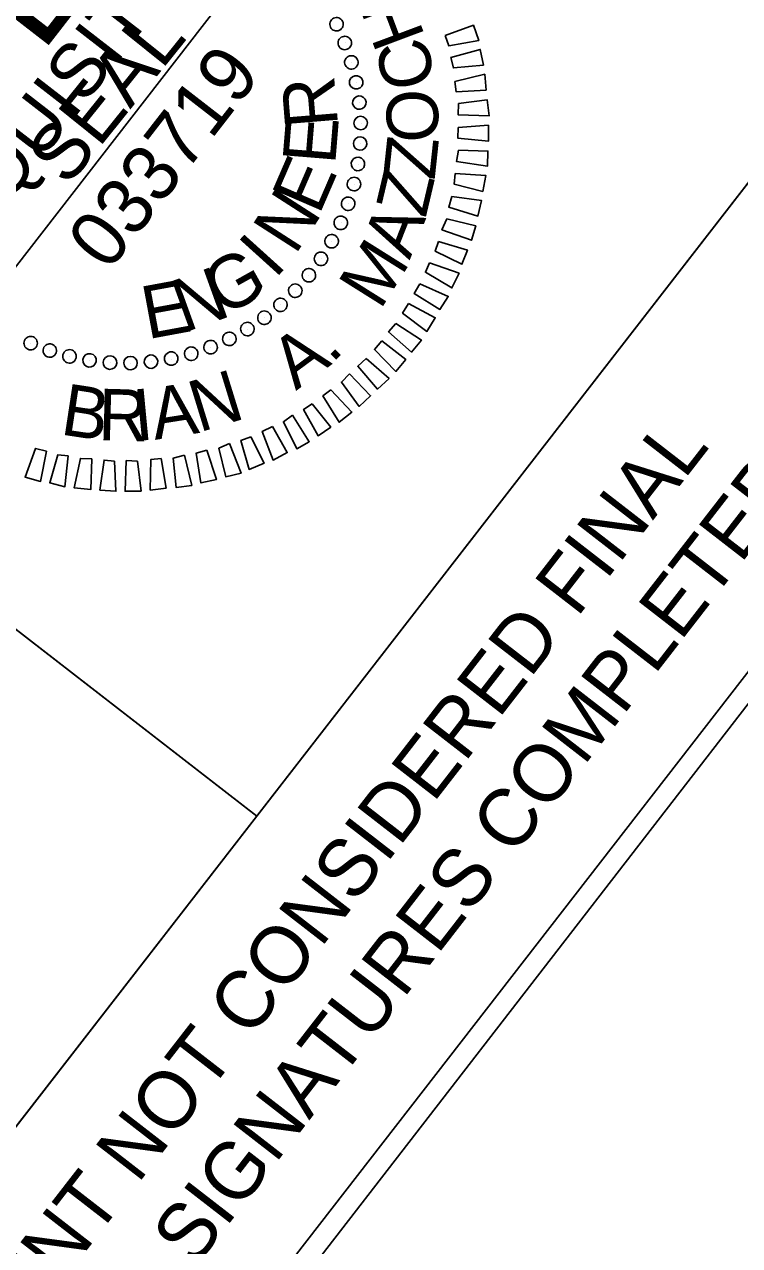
# Model space of a CAD drawing. Extents: x 2013373 to 2015284, y 444618 to 446636.
# Drawn here: x 2014451.4 to 2014527.7, y 446383.7 to 446513.9 of the extents above; entities that cross this region are included whole.
import ezdxf

# ---------------------------------------------------------------- set-up
doc = ezdxf.new("R2010")
doc.units = 0
for name, color, linetype in [('Old_Level_15', 7, 'Continuous'), ('Prop Conc 2ft 9in Curb and Gutter', 7, 'Continuous'), ('Prop Horizontal Alignment', 7, 'Continuous'), ('Prop Horizontal Alignment Tick Large', 7, 'Continuous'), ('Prop Noise Wall', 7, 'Continuous'), ('Scratch_Level_3', 7, 'Continuous')]:
    doc.layers.add(name, color=color, linetype=linetype)

msp = doc.modelspace()

# ---------------------------------------------------------------- linework, layer by layer
at = {"layer": 'Old_Level_15'}
for p, q in [((2014485.67, 446511.97), (2014485.67, 446511.97)), ((2014486.33, 446509.88), (2014486.33, 446509.88)), ((2014486.88, 446507.74), (2014486.88, 446507.74)), ((2014487.19, 446505.61), (2014487.19, 446505.61)), ((2014462.23, 446502.88), (2014462.23, 446502.88)), ((2014487.36, 446503.38), (2014487.36, 446503.38)), ((2014487.28, 446501.23), (2014487.28, 446501.23)), ((2014487.02, 446499.03), (2014487.02, 446499.03)), ((2014486.62, 446496.87), (2014486.62, 446496.87)), ((2014486.02, 446494.8), (2014486.02, 446494.8)), ((2014485.21, 446492.78), (2014485.21, 446492.78)), ((2014484.18, 446490.79), (2014484.18, 446490.79)), ((2014483.1, 446488.91), (2014483.1, 446488.91)), ((2014481.79, 446487.14), (2014481.79, 446487.14)), ((2014480.32, 446485.49), (2014480.32, 446485.49)), ((2014478.73, 446484.01), (2014478.73, 446484.01)), ((2014477.08, 446482.63), (2014477.08, 446482.63)), ((2014473.31, 446480.37), (2014473.31, 446480.37)), ((2014475.24, 446481.4), (2014475.24, 446481.4)), ((2014452.13, 446479.9), (2014452.13, 446479.9)), ((2014454.15, 446479.09), (2014454.15, 446479.09)), ((2014471.32, 446479.44), (2014471.32, 446479.44)), ((2014456.22, 446478.49), (2014456.22, 446478.49)), ((2014458.38, 446478.09), (2014458.38, 446478.09)), ((2014460.58, 446477.83), (2014460.58, 446477.83)), ((2014462.73, 446477.75), (2014462.73, 446477.75)), ((2014464.96, 446477.92), (2014464.96, 446477.92)), ((2014467.09, 446478.23), (2014467.09, 446478.23)), ((2014469.23, 446478.78), (2014469.23, 446478.78))]:
    msp.add_line(p, q, dxfattribs=at)
for points in [[(2014496.33, 446512.75), (2014499.33, 446513.84), (2014499.89, 446512.2), (2014496.69, 446511.65)], [(2014496.91, 446510.4), (2014500.05, 446511.26), (2014500.4, 446509.59), (2014497.2, 446509.29)], [(2014497.34, 446507.85), (2014500.53, 446508.61), (2014500.67, 446506.92), (2014497.49, 446506.73)], [(2014497.72, 446505.48), (2014500.8, 446505.87), (2014501.02, 446504.18), (2014497.69, 446504.3)], [(2014497.71, 446502.95), (2014500.93, 446503.17), (2014500.93, 446501.46), (2014497.65, 446501.8)], [(2014497.74, 446500.53), (2014500.88, 446500.42), (2014500.84, 446498.81), (2014497.54, 446499.29)], [(2014497.38, 446498.02), (2014500.64, 446497.83), (2014500.32, 446496.11), (2014497.27, 446496.9)], [(2014497.01, 446495.59), (2014500.2, 446495.13), (2014499.8, 446493.48), (2014496.69, 446494.44)], [(2014496.49, 446493.2), (2014499.58, 446492.45), (2014499.13, 446490.9), (2014495.96, 446492.03)], [(2014495.62, 446490.78), (2014498.69, 446489.85), (2014498.1, 446488.35), (2014495.25, 446489.73)], [(2014494.66, 446488.48), (2014497.79, 446487.38), (2014497.03, 446485.82), (2014494.21, 446487.5)], [(2014493.62, 446486.25), (2014496.64, 446484.92), (2014495.75, 446483.52), (2014493.01, 446485.21)], [(2014492.39, 446484.17), (2014495.26, 446482.64), (2014494.37, 446481.18), (2014491.77, 446483.13)], [(2014491.06, 446482.04), (2014493.78, 446480.25), (2014492.73, 446478.97), (2014490.28, 446481.12)], [(2014489.55, 446480.17), (2014492.11, 446478.18), (2014491.06, 446476.91), (2014488.77, 446479.26)], [(2014487.9, 446478.29), (2014490.34, 446476.14), (2014489.09, 446475.02), (2014487, 446477.47)], [(2014486.11, 446476.64), (2014488.36, 446474.32), (2014487.15, 446473.17), (2014485.25, 446475.78)], [(2014484.11, 446474.96), (2014486.37, 446472.57), (2014485.02, 446471.48), (2014483.27, 446474.29)], [(2014482.13, 446473.46), (2014484.12, 446470.97), (2014482.77, 446470.05), (2014481.21, 446472.85)], [(2014480.04, 446472.24), (2014481.82, 446469.4), (2014480.49, 446468.66), (2014479.06, 446471.54)], [(2014475.59, 446469.93), (2014477.01, 446467.12), (2014475.42, 446466.45), (2014474.53, 446469.55)], [(2014477.91, 446471.04), (2014479.47, 446468.25), (2014477.97, 446467.45), (2014476.8, 446470.51)], [(2014453.79, 446468.42), (2014453.17, 446465.17), (2014451.51, 446465.64), (2014452.62, 446468.7)], [(2014473.33, 446469.22), (2014474.55, 446466.05), (2014472.92, 446465.67), (2014472.18, 446468.71)], [(2014456.1, 446467.89), (2014455.77, 446464.61), (2014454.15, 446465.04), (2014454.99, 446468)], [(2014458.64, 446467.57), (2014458.52, 446464.31), (2014456.75, 446464.48), (2014457.42, 446467.63)], [(2014461.06, 446467.34), (2014461.21, 446464.12), (2014459.49, 446464.26), (2014459.94, 446467.45)], [(2014463.52, 446467.33), (2014463.88, 446464.14), (2014462.17, 446464.13), (2014462.3, 446467.39)], [(2014466.01, 446467.61), (2014466.55, 446464.47), (2014464.87, 446464.26), (2014464.92, 446467.51)], [(2014468.5, 446467.96), (2014469.29, 446464.75), (2014467.61, 446464.54), (2014467.32, 446467.67)], [(2014470.89, 446468.51), (2014471.92, 446465.37), (2014470.26, 446465.01), (2014469.75, 446468.19)]]:
    msp.add_lwpolyline(points, close=True, dxfattribs=at)
for centre, major_axis in [((2014484.73, 446513.95), (0.646, 0.318)), ((2014485.61, 446511.95), (0.671, 0.26)), ((2014486.31, 446509.88), (0.691, 0.201)), ((2014486.83, 446507.75), (0.706, 0.14)), ((2014487.16, 446505.59), (0.716, 0.078)), ((2014487.3, 446503.41), (0.72, 0.015)), ((2014487.25, 446501.22), (0.718, -0.048)), ((2014487.01, 446499.04), (0.712, -0.11)), ((2014486.59, 446496.9), (0.699, -0.172)), ((2014485.97, 446494.8), (0.682, -0.232)), ((2014485.18, 446492.76), (0.659, -0.29)), ((2014484.21, 446490.8), (0.631, -0.347)), ((2014483.07, 446488.93), (0.598, -0.4)), ((2014481.78, 446487.17), (0.561, -0.451)), ((2014480.33, 446485.52), (0.52, -0.498)), ((2014478.75, 446484.01), (0.474, -0.542)), ((2014477.04, 446482.64), (0.425, -0.581)), ((2014475.22, 446481.43), (0.373, -0.616)), ((2014452.11, 446479.93), (-0.29, -0.659)), ((2014471.3, 446479.5), (0.26, -0.671)), ((2014473.3, 446480.38), (0.318, -0.646)), ((2014454.15, 446479.14), (-0.232, -0.682)), ((2014456.25, 446478.52), (-0.172, -0.699)), ((2014467.1, 446478.28), (0.14, -0.706)), ((2014469.23, 446478.8), (0.201, -0.691)), ((2014458.39, 446478.09), (-0.11, -0.712)), ((2014460.57, 446477.85), (-0.048, -0.718)), ((2014462.76, 446477.8), (0.015, -0.72)), ((2014464.94, 446477.95), (0.078, -0.716))]:
    msp.add_ellipse(centre, major_axis=major_axis, ratio=0.999708, dxfattribs=at)
at = {"layer": 'Prop Horizontal Alignment'}
msp.add_line((2014387.32, 446498.4), (2014476.18, 446429.49), dxfattribs=at)
for points in [[(2014387.32, 446498.4), (2014448.6, 446577.42), (2014537.5, 446508.48), (2014476.22, 446429.46)], [(2014326.01, 446419.34), (2014387.32, 446498.4), (2014476.22, 446429.46), (2014414.9, 446350.4)]]:
    msp.add_lwpolyline(points, close=True, dxfattribs=at)
at = {"layer": 'Prop Horizontal Alignment Tick Large'}
msp.add_lwpolyline([(2014386.73, 446405.85), (2014368.16, 446420.25), (2014458.24, 446536.41), (2014476.81, 446522.01)], close=True, dxfattribs=at)
at = {"layer": 'Prop Noise Wall'}
msp.add_lwpolyline([(2014144.54, 446243.36), (2013513.08, 445427.57), (2013603.78, 445375.37), (2013612.37, 445329.9), (2013915.76, 445258.44), (2014041.96, 445083.42), (2014361.11, 444814.86), (2015247.36, 445957.62), (2014564.18, 446487.45), (2014441.6, 446328.92), (2014350.52, 446399.67), (2014197.18, 446202.42)], close=True, dxfattribs=at)
at = {"layer": 'Scratch_Level_3'}
for p, q in [((2014414.89, 446350.41), (2014537.49, 446508.49)), ((2014562.76, 446488.89), (2014440.16, 446330.81))]:
    msp.add_line(p, q, dxfattribs=at)

# ---------------------------------------------------------------- texts
at = {"layer": 'Old_Level_15'}
for s, height, rotation, p in [('SEAL', 5.998, 51.2051, (2014456.02, 446496.5)), ('R', 5.64, 94.6865, (2014484.9, 446503.14)), ('E', 5.64, 85.3292, (2014484.58, 446498.9)), ('E', 5.64, 66.6169, (2014482.87, 446493.51)), ('N', 5.64, 57.2615, (2014480.31, 446489.23)), ('I', 5.64, 47.9063, (2014478.14, 446486.68)), ('G', 5.64, 29.1953, (2014472.62, 446482.67)), ('N', 5.64, 19.8391, (2014468.52, 446481.04)), ('E', 5.64, 10.482, (2014464.55, 446480.33))]:
    msp.add_text(s, height=height, rotation=rotation, dxfattribs=at).set_placement(p)
at = {"layer": 'Prop Conc 2ft 9in Curb and Gutter'}
for s, height, rotation, p in [('H', 5.5, 110.5529, (2014494.2, 446512.65)), ('C', 5.5, 101.6802, (2014495.32, 446507.6)), ('033719', 5.998, 52.2051, (2014460.4, 446487.45)), ('O', 5.5, 90.9757, (2014495.62, 446501.37)), ('Z', 5.5, 83.8489, (2014495.18, 446497.24)), ('Z', 5.5, 76.7221, (2014494.22, 446493.2)), ('A', 5.5, 68.5363, (2014492.52, 446488.74)), ('M', 5.5, 57.8605, (2014489.38, 446483.37)), ('A', 5.5, 36.4944, (2014480.4, 446474.82)), ('.', 5.5, 44.6802, (2014484.21, 446477.7)), ('N', 5.5, 17.1175, (2014470.07, 446470.38)), ('B', 5.5, 351.358, (2014455.16, 446470.21)), ('R', 5.5, 358.4848, (2014459.27, 446469.58)), ('I', 5.5, 5.4113, (2014463.31, 446469.47)), ('A', 5.5, 8.9317, (2014465.36, 446469.6))]:
    msp.add_text(s, height=height, rotation=rotation, dxfattribs=at).set_placement(p)
at = {"layer": 'Prop Horizontal Alignment Tick Large'}
for s, height, p in [('INCOMPLETE PLANS', 11.52, (2014382.97, 446420.09)), ('DO NOT USE FOR R/W ACQUISITION', 5.76, (2014390.45, 446418.4))]:
    msp.add_text(s, height=height, rotation=52.2051, dxfattribs=at).set_placement(p)
at = {"layer": 'Scratch_Level_3'}
for s, p in [('DOCUMENT NOT CONSIDERED FINAL', (2014433.14, 446350.97)), ('UNLESS ALL SIGNATURES COMPLETED', (2014437.74, 446340.15))]:
    msp.add_text(s, height=6.124, rotation=52.2051, dxfattribs=at).set_placement(p)

doc.saveas('drawing.dxf')
